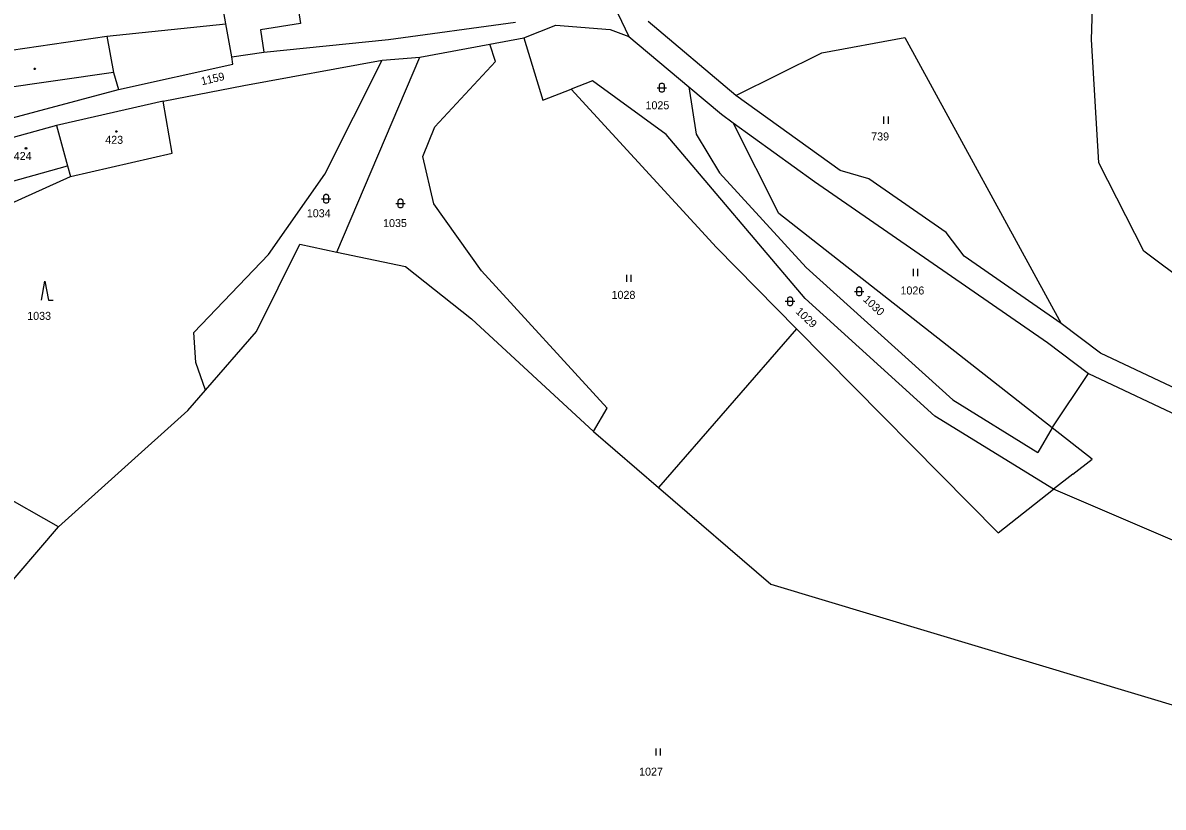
# Model space of a CAD drawing. Extents: x -812394 to -807601, y -1013097 to -1009266.
# Drawn here: x -810997.7 to -810755.5, y -1011891.2 to -1011724.6 of the extents above; entities that cross this region are included whole.
import ezdxf

# ---------------------------------------------------------------- set-up
doc = ezdxf.new("R2010")
doc.units = 0
for name, color, linetype in [('Default', 7, 'Continuous'), ('KN_HRANICE', 7, 'Continuous'), ('KN_KULTURY', 7, 'Continuous'), ('KN_PARCELY', 7, 'Continuous'), ('KN_SLUCKY', 7, 'Continuous')]:
    doc.layers.add(name, color=color, linetype=linetype)

# ---------------------------------------------------------------- blocks, each defined once
blk = doc.blocks.new('306')
at = {"layer": 'Default'}
for p, q in [((-0.5, 1.5), (-0.5, 0)), ((0.5, 0), (0.5, 1.5))]:
    blk.add_line(p, q, dxfattribs=at)
blk = doc.blocks.new('308')
at = {"layer": 'Default'}
blk.add_lwpolyline([(-0.75, 0), (0, 4), (0.75, 0), (1.75, 0)], dxfattribs=at)
blk = doc.blocks.new('316')
at = {"layer": 'Default'}
for points in [[(-1, 1), (0.27, 1), (1, 1)], [(-0.5, 1.5), (-0.4, 1.79), (-0.15, 1.97), (0.16, 1.97), (0.41, 1.79), (0.51, 1.5), (0.51, 0.5), (0.41, 0.21), (0.16, 0.03), (-0.15, 0.03), (-0.4, 0.21), (-0.5, 0.5), (-0.5, 1.5)]]:
    blk.add_lwpolyline(points, dxfattribs=at)
blk = doc.blocks.new('NAHRADNI_SYMBOL')
at = {"layer": 'Default'}
blk.add_lwpolyline([(0.09, 0.15), (0.18, 0), (0.09, -0.15), (-0.09, -0.15), (-0.18, 0), (-0.09, 0.15), (0.09, 0.15)], dxfattribs=at)
blk = doc.blocks.new('402')
at = {"layer": 'Default'}
blk.add_lwpolyline([(0.09, 0.15), (0.18, 0), (0.09, -0.15), (-0.09, -0.15), (-0.18, 0), (-0.09, 0.15), (0.09, 0.15)], dxfattribs=at)

msp = doc.modelspace()

# ---------------------------------------------------------------- linework, layer by layer
at = {"layer": 'KN_HRANICE'}
for p, q in [((-810770.67, -1011728.15), (-810769.26, -1011682.72)), ((-810940.3, -1011714.57), (-810938.7, -1011724.76)), ((-810873.63, -1011717.68), (-810868.94, -1011727.48)), ((-810938.7, -1011724.76), (-810947.2, -1011726.09)), ((-810920.02, -1011728.18), (-810893.06, -1011724.45)), ((-810846.21, -1011740.05), (-810864.89, -1011724.35)), ((-810947.2, -1011726.09), (-810946.5, -1011730.84)), ((-810891.27, -1011727.77), (-810884.49, -1011725.13)), ((-810884.49, -1011725.13), (-810872.93, -1011726.05)), ((-810872.93, -1011726.05), (-810868.94, -1011727.48)), ((-810946.5, -1011730.84), (-810920.02, -1011728.18)), ((-810913.39, -1011731.87), (-810898.52, -1011729.11)), ((-810898.52, -1011729.11), (-810891.27, -1011727.77)), ((-810897.26, -1011732.84), (-810898.52, -1011729.11)), ((-810891.27, -1011727.77), (-810887.22, -1011741.06)), ((-810868.94, -1011727.48), (-810856.2, -1011738.19)), ((-810827.94, -1011730.95), (-810810.37, -1011727.72)), ((-810810.37, -1011727.72), (-810777.11, -1011788.45)), ((-810769.15, -1011754.35), (-810770.67, -1011728.15)), ((-810953.32, -1011731.84), (-810946.5, -1011730.84)), ((-810953.08, -1011733.36), (-810953.32, -1011731.84)), ((-810931, -1011773.27), (-810913.39, -1011731.87)), ((-810921.33, -1011732.51), (-810913.39, -1011731.87)), ((-810846.21, -1011740.05), (-810827.94, -1011730.95)), ((-810977.33, -1011738.74), (-810953.08, -1011733.36)), ((-810950.77, -1011737.88), (-810921.33, -1011732.51)), ((-810910.16, -1011746.66), (-810897.26, -1011732.84)), ((-811010.19, -1011747.48), (-810977.33, -1011738.74)), ((-810967.84, -1011741.23), (-810950.77, -1011737.88)), ((-810887.22, -1011741.06), (-810881.22, -1011738.72)), ((-810881.22, -1011738.72), (-810850.37, -1011772.33)), ((-810856.2, -1011738.19), (-810854.67, -1011748.28)), ((-810856.2, -1011738.19), (-810849.29, -1011744)), ((-810967.84, -1011741.23), (-810990.56, -1011746.41)), ((-810824.08, -1011755.96), (-810846.21, -1011740.05)), ((-810849.29, -1011744), (-810846.78, -1011745.82)), ((-810990.56, -1011746.41), (-811006.21, -1011750.72)), ((-810990.56, -1011746.41), (-810988.18, -1011754.95)), ((-810846.78, -1011745.82), (-810829.53, -1011758.27)), ((-810837.1, -1011765.11), (-810846.78, -1011745.82)), ((-810912.73, -1011753.01), (-810910.16, -1011746.66)), ((-810910.4, -1011763.04), (-810912.73, -1011753.01)), ((-810988.18, -1011754.95), (-810987.54, -1011757.25)), ((-810818.01, -1011757.72), (-810824.08, -1011755.96)), ((-810759.6, -1011773.11), (-810769.15, -1011754.35)), ((-811005.63, -1011765.4), (-810987.54, -1011757.25)), ((-810829.53, -1011758.27), (-810780.03, -1011792.51)), ((-810801.56, -1011769.1), (-810818.01, -1011757.72)), ((-810900.26, -1011777.28), (-810910.4, -1011763.04)), ((-810779.05, -1011810.59), (-810837.1, -1011765.11)), ((-810797.76, -1011774.16), (-810801.56, -1011769.1)), ((-810948.07, -1011790.14), (-810938.83, -1011771.61)), ((-810938.83, -1011771.61), (-810931, -1011773.27)), ((-810850.37, -1011772.33), (-810833.33, -1011789.58)), ((-810734.95, -1011791.55), (-810759.6, -1011773.11)), ((-810931, -1011773.27), (-810916.4, -1011776.38)), ((-810777.11, -1011788.45), (-810797.76, -1011774.16)), ((-810916.4, -1011776.38), (-810902.39, -1011787.45)), ((-810873.56, -1011806.45), (-810900.26, -1011777.28)), ((-810902.39, -1011787.45), (-810876.5, -1011811.36)), ((-810958.86, -1011802.61), (-810948.07, -1011790.14)), ((-810833.33, -1011789.58), (-810862.64, -1011823.29)), ((-810833.33, -1011789.58), (-810790.53, -1011832.9)), ((-810768.74, -1011794.72), (-810777.11, -1011788.45)), ((-810960.96, -1011796.71), (-810961.35, -1011790.39)), ((-810780.03, -1011792.51), (-810771.3, -1011799.04)), ((-810990.1, -1011831.63), (-811055.79, -1011794.38)), ((-810738.04, -1011809.35), (-810768.74, -1011794.72)), ((-810958.86, -1011802.61), (-810960.96, -1011796.71)), ((-810779.05, -1011810.59), (-810771.3, -1011799.04)), ((-810771.3, -1011799.04), (-810722.88, -1011822.01)), ((-810962.6, -1011806.94), (-810958.86, -1011802.61)), ((-810990.1, -1011831.63), (-810962.6, -1011806.94)), ((-810876.5, -1011811.36), (-810873.56, -1011806.45)), ((-810876.5, -1011811.36), (-810862.64, -1011823.29)), ((-810779.05, -1011810.59), (-810782.06, -1011815.84)), ((-810770.57, -1011817.24), (-810779.05, -1011810.59)), ((-810774.63, -1011820.43), (-810770.57, -1011817.24)), ((-810774.63, -1011820.43), (-810778.75, -1011823.66)), ((-810862.64, -1011823.29), (-810838.82, -1011843.8)), ((-810790.53, -1011832.9), (-810778.75, -1011823.66)), ((-810735.32, -1011842.24), (-810778.75, -1011823.66)), ((-811014.6, -1011860.1), (-810990.1, -1011831.63)), ((-810838.82, -1011843.8), (-810681.36, -1011891.15))]:
    msp.add_line(p, q, dxfattribs=at)
for points in [[(-810961.35, -1011790.39), (-810945.5, -1011773.77), (-810933.55, -1011756.72), (-810921.33, -1011732.51)], [(-810778.75, -1011823.66), (-810803.98, -1011808.11), (-810831.53, -1011783.14), (-810861.05, -1011748.31), (-810876.68, -1011736.95), (-810881.22, -1011738.72)], [(-810987.54, -1011757.25), (-810965.94, -1011752.29), (-810967.84, -1011741.23)], [(-810854.67, -1011748.28), (-810849.68, -1011756.49), (-810831.3, -1011776.59), (-810800.17, -1011804.67), (-810782.06, -1011815.84)]]:
    msp.add_lwpolyline(points, dxfattribs=at)
at = {"layer": 'KN_SLUCKY'}
for p, q in [((-810954.56, -1011724.79), (-810956.56, -1011713.43)), ((-810979.82, -1011727.46), (-810954.56, -1011724.79)), ((-810953.32, -1011731.84), (-810954.56, -1011724.79)), ((-811012.33, -1011732.15), (-810979.82, -1011727.46)), ((-810979.82, -1011727.46), (-810978.44, -1011735.16)), ((-810978.44, -1011735.16), (-811011.17, -1011739.82)), ((-810978.44, -1011735.16), (-810977.33, -1011738.74))]:
    msp.add_line(p, q, dxfattribs=at)
msp.add_lwpolyline([(-811006.21, -1011750.72), (-811003.67, -1011759.26), (-810988.18, -1011754.95)], dxfattribs=at)

# ---------------------------------------------------------------- block references
at = {"layer": 'KN_KULTURY'}
for name, p in [('402', (-810995.15, -1011734.38)), ('316', (-810861.96, -1011739.38)), ('306', (-810814.34, -1011746.03)), ('NAHRADNI_SYMBOL', (-810977.8, -1011747.67)), ('402', (-810997.02, -1011751.26)), ('316', (-810933.27, -1011762.96)), ('316', (-810917.47, -1011763.95)), ('306', (-810868.96, -1011779.6)), ('306', (-810808.04, -1011778.37)), ('308', (-810993, -1011783.47)), ('316', (-810834.72, -1011784.74)), ('316', (-810820.04, -1011782.64)), ('306', (-810862.75, -1011880.17))]:
    msp.add_blockref(name, p, dxfattribs=at)

# ---------------------------------------------------------------- texts
at = {"layer": 'KN_PARCELY'}
for s, rotation, p in [('1159', 13.293, (-810959.63, -1011737.88)), ('1030', 317.018, (-810819.33, -1011783.52)), ('1029', 316.674, (-810833.67, -1011786.08))]:
    msp.add_text(s, height=1.7, rotation=rotation, dxfattribs=at).set_placement(p)
for s, p in [('1025', (-810865.42, -1011742.96)), ('423', (-810980.18, -1011750.3)), ('739', (-810817.48, -1011749.58)), ('424', (-810999.61, -1011753.73)), ('1034', (-810937.36, -1011765.89)), ('1035', (-810921.16, -1011767.97)), ('1028', (-810872.63, -1011783.22)), ('1026', (-810811.26, -1011782.29)), ('1033', (-810996.75, -1011787.68)), ('1027', (-810866.78, -1011884.46))]:
    msp.add_text(s, height=1.7, dxfattribs=at).set_placement(p)

doc.saveas('drawing.dxf')
